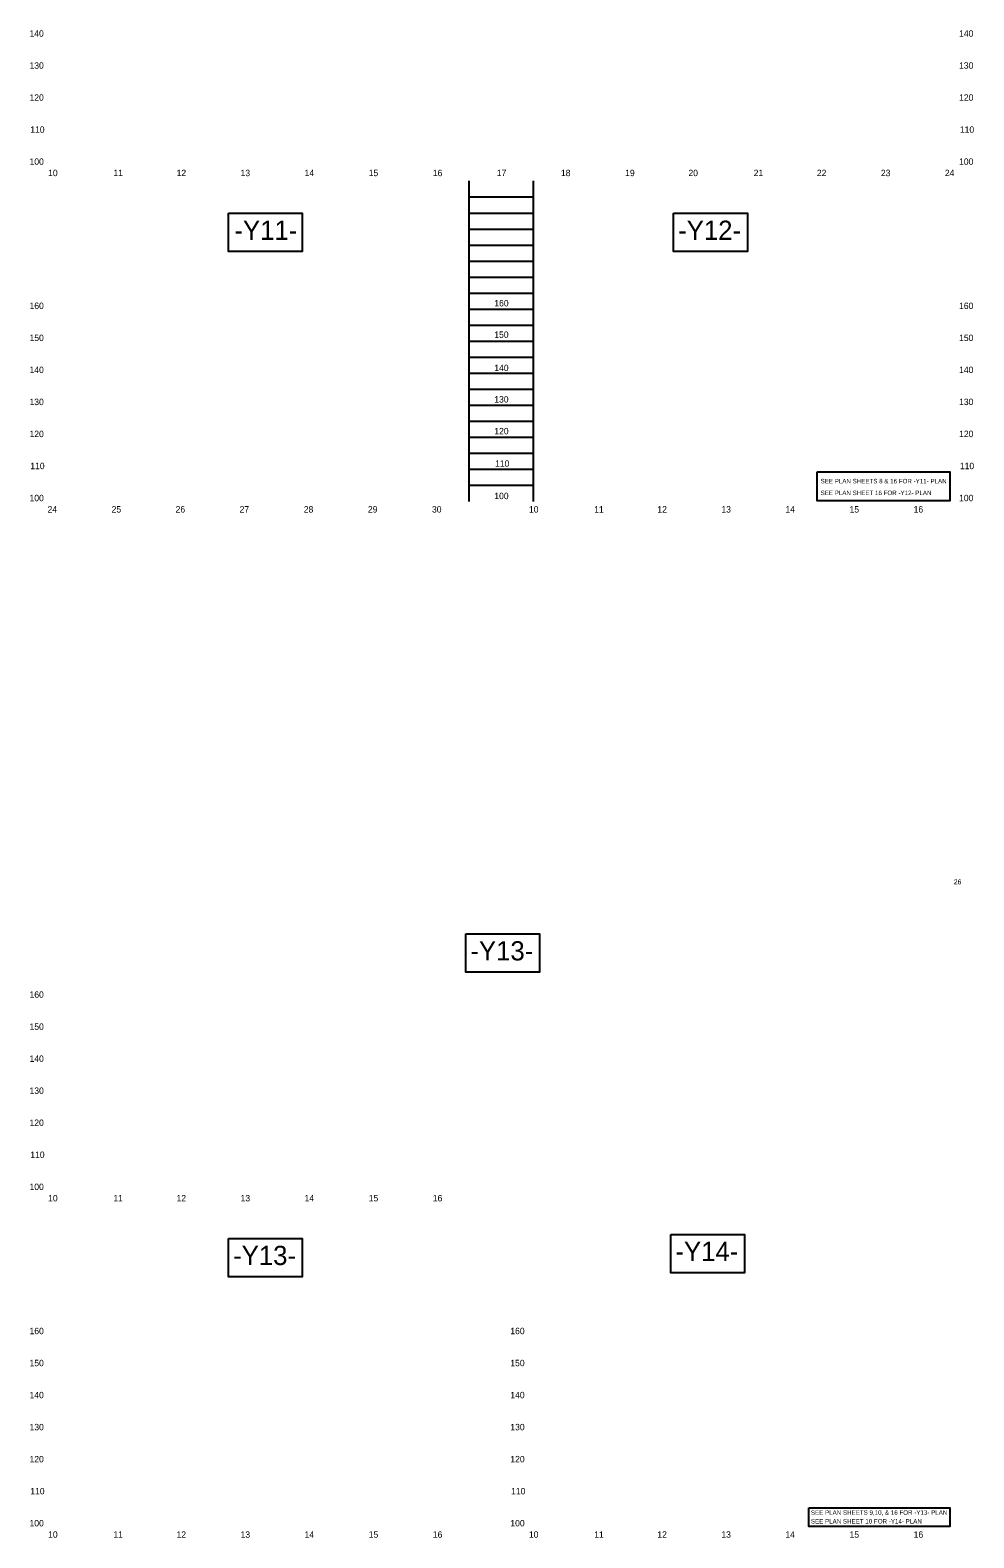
# Model space of a CAD drawing. Extents: x 2364289 to 2366249, y 588759 to 610062.
# Drawn here: x 2364480 to 2365952, y 591434 to 593787 of the extents above; entities that cross this region are included whole.
import ezdxf

# ---------------------------------------------------------------- set-up
doc = ezdxf.new("R2010")
doc.units = 0
for name, color, linetype in [('Exist Vertical Profile Horizontal Axis Label Major', 7, 'Continuous'), ('Exist Vertical Profile Vertical Axis Label', 7, 'Continuous'), ('Prop DSN Text', 7, 'Continuous'), ('Prop Grid Mask', 7, 'Continuous'), ('Sheet Data Field CELL', 7, 'Continuous'), ('Sheet Profile CELL', 7, 'Continuous'), ('Sheet Profile Grid Major CELL', 7, 'Continuous'), ('Sheet Profile Grid Middle CELL', 7, 'Continuous')]:
    doc.layers.add(name, color=color, linetype=linetype)

msp = doc.modelspace()

# ---------------------------------------------------------------- linework, layer by layer
at = {"layer": 'Prop Grid Mask'}
for points in [[(2364789.5, 593501.1), (2364904.6, 593501.1), (2364904.6, 593441.3), (2364789.5, 593441.3)], [(2365483.7, 593501.1), (2365598.9, 593501.1), (2365598.9, 593441.3), (2365483.7, 593441.3)], [(2365708, 593097.3), (2365914.6, 593097.3), (2365914.6, 593052.3), (2365708, 593052.3)], [(2365159.6, 592376.5), (2365274.8, 592376.5), (2365274.8, 592316.6), (2365159.6, 592316.6)], [(2364789.5, 591901.1), (2364904.6, 591901.1), (2364904.6, 591841.3), (2364789.5, 591841.3)], [(2365479.4, 591907.4), (2365594.6, 591907.4), (2365594.6, 591847.6), (2365479.4, 591847.6)], [(2365694.8, 591480.9), (2365914.6, 591480.9), (2365914.6, 591451.5), (2365694.8, 591451.5)]]:
    msp.add_lwpolyline(points, close=True, dxfattribs=at)
at = {"layer": 'Sheet Profile CELL'}
for p, q in [((2365164.6, 593551.5), (2365164.6, 593051.5)), ((2365264.6, 593551.5), (2365264.6, 593051.5))]:
    msp.add_line(p, q, dxfattribs=at)
at = {"layer": 'Sheet Profile Grid Major CELL'}
for p, q in [((2365164.6, 593501.5), (2365264.6, 593501.5)), ((2365164.6, 593451.5), (2365264.6, 593451.5)), ((2365164.6, 593401.5), (2365264.6, 593401.5)), ((2365164.6, 593351.5), (2365264.6, 593351.5)), ((2365164.6, 593301.5), (2365264.6, 593301.5)), ((2365164.6, 593251.5), (2365264.6, 593251.5)), ((2365164.6, 593201.5), (2365264.6, 593201.5)), ((2365164.6, 593151.5), (2365264.6, 593151.5)), ((2365164.6, 593101.5), (2365264.6, 593101.5))]:
    msp.add_line(p, q, dxfattribs=at)
at = {"layer": 'Sheet Profile Grid Middle CELL'}
for p, q in [((2365164.6, 593526.5), (2365264.6, 593526.5)), ((2365164.6, 593476.5), (2365264.6, 593476.5)), ((2365164.6, 593426.5), (2365264.6, 593426.5)), ((2365164.6, 593376.5), (2365264.6, 593376.5)), ((2365164.6, 593326.5), (2365264.6, 593326.5)), ((2365164.6, 593276.5), (2365264.6, 593276.5)), ((2365164.6, 593226.5), (2365264.6, 593226.5)), ((2365164.6, 593176.5), (2365264.6, 593176.5)), ((2365164.6, 593126.5), (2365264.6, 593126.5)), ((2365164.6, 593076.5), (2365264.6, 593076.5))]:
    msp.add_line(p, q, dxfattribs=at)

# ---------------------------------------------------------------- texts
at = {"layer": 'Exist Vertical Profile Horizontal Axis Label Major'}
for s, p in [('10', (2364508.2, 593559)), ('10', (2364508.2, 593559)), ('11', (2364610, 593559)), ('11', (2364610.1, 593559)), ('11', (2364610.1, 593559)), ('12', (2364708.5, 593559)), ('12', (2364708.7, 593559)), ('12', (2364708.7, 593559)), ('13', (2364808.4, 593559)), ('13', (2364808.4, 593559)), ('13', (2364808.4, 593559)), ('14', (2364908.2, 593559)), ('14', (2364908.2, 593559)), ('14', (2364908.2, 593559)), ('15', (2365008.3, 593559)), ('15', (2365008.3, 593559)), ('15', (2365008.3, 593559)), ('16', (2365108.3, 593559)), ('16', (2365108.3, 593559)), ('16', (2365108.3, 593559)), ('16', (2365108.3, 593559)), ('17', (2365208.1, 593559)), ('17', (2365208.1, 593559)), ('17', (2365208.1, 593559)), ('18', (2365308.2, 593559)), ('18', (2365308.2, 593559)), ('18', (2365308.2, 593559)), ('19', (2365408.3, 593559)), ('19', (2365408.3, 593559)), ('19', (2365408.3, 593559)), ('20', (2365507, 593559)), ('20', (2365507, 593559)), ('20', (2365507, 593559)), ('21', (2365608.8, 593559)), ('21', (2365608.8, 593559)), ('21', (2365608.8, 593559)), ('22', (2365707.3, 593559)), ('22', (2365707.3, 593559)), ('22', (2365707.3, 593559)), ('23', (2365807.2, 593559)), ('23', (2365807.2, 593559)), ('23', (2365807.2, 593559)), ('24', (2365907, 593559)), ('24', (2365907, 593559)), ('24', (2365907, 593559)), ('24', (2364507.3, 593034)), ('25', (2364607.3, 593034)), ('26', (2364707.1, 593034)), ('27', (2364806.9, 593034)), ('28', (2364907, 593034)), ('29', (2365007.1, 593034)), ('30', (2365107, 593034)), ('10', (2365258.2, 593034)), ('10', (2365258.2, 593034)), ('11', (2365360, 593034)), ('11', (2365360.1, 593034)), ('11', (2365360.1, 593034)), ('12', (2365458.5, 593034)), ('12', (2365458.7, 593034)), ('12', (2365458.7, 593034)), ('13', (2365558.4, 593034)), ('13', (2365558.4, 593034)), ('13', (2365558.4, 593034)), ('14', (2365658.2, 593034)), ('14', (2365658.2, 593034)), ('14', (2365658.2, 593034)), ('15', (2365758.3, 593034)), ('15', (2365758.3, 593034)), ('15', (2365758.3, 593034)), ('16', (2365858.3, 593034)), ('10', (2364508.2, 591959)), ('11', (2364610, 591959)), ('12', (2364708.5, 591959)), ('13', (2364808.4, 591959)), ('14', (2364908.2, 591959)), ('15', (2365008.3, 591959)), ('16', (2365108.3, 591959)), ('10', (2364508.2, 591434)), ('11', (2364610, 591434)), ('12', (2364708.5, 591434)), ('13', (2364808.4, 591434)), ('14', (2364908.2, 591434)), ('15', (2365008.3, 591434)), ('16', (2365108.3, 591434)), ('10', (2365258.2, 591434)), ('11', (2365360, 591434)), ('12', (2365458.5, 591434)), ('13', (2365558.4, 591434)), ('14', (2365658.2, 591434)), ('15', (2365758.3, 591434)), ('16', (2365858.3, 591434))]:
    msp.add_text(s, height=10, dxfattribs=at).set_placement(p)
at = {"layer": 'Exist Vertical Profile Vertical Axis Label'}
for s, p in [('140', (2364479.2, 593776.7)), ('140', (2365929.2, 593776.7)), ('130', (2364479.2, 593726.7)), ('130', (2365929.2, 593726.7)), ('120', (2364479.2, 593676.7)), ('120', (2365929.2, 593676.7)), ('110', (2364480.4, 593626.7)), ('110', (2365930.4, 593626.7)), ('100', (2364479.2, 593576.7)), ('100', (2365929.2, 593576.7)), ('160', (2364479.2, 593351.7)), ('160', (2365204.2, 593355.7)), ('160', (2365929.2, 593351.7)), ('150', (2364479.2, 593301.7)), ('150', (2365204.2, 593306.6)), ('150', (2365929.2, 593301.7)), ('140', (2364479.2, 593251.7)), ('140', (2365204.2, 593254.7)), ('140', (2365929.2, 593251.7)), ('130', (2364479.2, 593201.7)), ('130', (2365204.2, 593205.7)), ('130', (2365929.2, 593201.7)), ('120', (2364479.2, 593151.7)), ('120', (2365204.2, 593156.1)), ('120', (2365929.2, 593151.7)), ('110', (2364480.4, 593101.7)), ('110', (2365205.4, 593105.4)), ('110', (2365930.4, 593101.7)), ('100', (2364479.2, 593051.7)), ('100', (2365204.2, 593054.9)), ('100', (2365929.2, 593051.7)), ('160', (2364479.2, 592276.7)), ('150', (2364479.2, 592226.7)), ('140', (2364479.2, 592176.7)), ('130', (2364479.2, 592126.7)), ('120', (2364479.2, 592076.7)), ('110', (2364480.4, 592026.7)), ('100', (2364479.2, 591976.7)), ('160', (2364479.2, 591751.7)), ('160', (2365229.2, 591751.7)), ('150', (2364479.2, 591701.7)), ('150', (2365229.2, 591701.7)), ('140', (2364479.2, 591651.7)), ('140', (2365229.2, 591651.7)), ('130', (2364479.2, 591601.7)), ('130', (2365229.2, 591601.7)), ('120', (2364479.2, 591551.7)), ('120', (2365229.2, 591551.7)), ('110', (2364480.4, 591501.7)), ('110', (2365230.4, 591501.7)), ('100', (2364479.2, 591451.7)), ('100', (2365229.2, 591451.7))]:
    msp.add_text(s, height=10, dxfattribs=at).set_placement(p)
at = {"layer": 'Prop DSN Text'}
for s, p in [('SEE PLAN SHEETS 8 & 16 FOR -Y11- PLAN', (2365713.2, 593079.6)), ('SEE PLAN SHEET 16 FOR -Y12- PLAN', (2365713.2, 593061.2)), ('SEE PLAN SHEETS 9,10, & 16 FOR -Y13- PLAN', (2365698.1, 591469.8)), ('SEE PLAN SHEET 10 FOR -Y14- PLAN', (2365698.1, 591456.2))]:
    msp.add_text(s, height=7, dxfattribs=at).set_placement(p)
at = {"layer": 'Prop Grid Mask'}
for s, p in [('-Y11-', (2364798.8, 593459.6)), ('-Y12-', (2365491, 593459.6)), ('-Y13-', (2365166.9, 592335)), ('-Y13-', (2364796.8, 591859.6)), ('-Y14-', (2365486.7, 591865.9))]:
    msp.add_text(s, height=30, dxfattribs=at).set_placement(p)
at = {"layer": 'Sheet Data Field CELL'}
msp.add_text('26', height=7.75, dxfattribs=at).set_placement((2365920.9, 592453.8))

doc.saveas('drawing.dxf')
